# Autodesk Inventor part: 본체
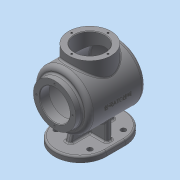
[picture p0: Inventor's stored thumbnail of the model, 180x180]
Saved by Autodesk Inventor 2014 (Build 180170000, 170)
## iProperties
Created: 2023-01
Part Number: 본체
Material: 일반
Document SubType Name: Modeling
Designer: dg
Density: 1 g/cm^3
Appearance: 기본값
Author: dg
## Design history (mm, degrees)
sketch "스케치1"
  geometry: L1 (0, 0)-(122, 0); L2 (0, 27)-(0, 38); L3 (0, 38)-(12, 38); L4 (12, 38)-(12, 50); L5 (12, 50)-(111.087, 50); L6 (0, 27)-(17, 27); L7 (17, 27)-(17, 45); L8 (17, 45)-(107.374, 45); A1 r 120 centre (2, 0) between (122, 0) and (111.087, 50); A2 r 110 centre (7, 0) between (117, 0) and (107.374, 45)
  constraints: 16 end point, 4 parallel, 4 point on circle, 3 perpendicular, 2 centre point, 2 horizontal alignment, 1 horizontal, 1 point on line, 1 vertical alignment
  dimensions: "d0" = 122 distance of L1.start L1.end; "d1" = 54 diameter of L6 L1; "d2" = 17 distance of L2.start L6.end; "d3" = 5 distance of L1.end A2.start; "d4" = 120 radius of A1; "d5" = 110 distance from line of L1.end L4; "d6" = 76 diameter of L3 L1; "d7" = 100 diameter of L5 L1; "d8" = 90 diameter of L8 L1; "d9" = 110 radius of A2
revolve "회전1" sketch "스케치1" stored, may be unused: angle "d10" = 90 deg
node "작업 평면1"
sketch "스케치2"
  geometry: L1 (0, 80)-(0, 46); L2 (-46, 80)-(-46, 46); L3 (46, 46)-(46, 80); A1 r 46 centre (0, 80) between (46, 80) and (-46, 80); A2 r 46 centre (0, 46) between (-46, 46) and (46, 46); 3 further points
  constraints: 8 end point, 5 point on circle, 4 tangent, 2 centre point, 1 coincident, 1 midpoint, 1 parallel, 1 vertical, 1 vertical alignment
  dimensions: "d12" = 126 dimension on A2 A1; "d13" = 92 distance between parallel lines of L3 L2
extrude "돌출1" join sketch "스케치2" distance "d14" = 10; taper "d15" = 0 deg
sketch "스케치3"
  geometry: L1 (-46, 80)-(-46, 46) reference; L2 (-35, 58)-(35, 58); L3 (35, 58)-(35, 68); L4 (35, 68)-(-35, 68); L5 (-35, 68)-(-35, 58); A1 r 46 centre (0, 80) between (46, 80) and (-46, 80) reference; 5 further points
  constraints: 8 end point, 3 midpoint, 2 parallel, 1 horizontal, 1 horizontal alignment, 1 perpendicular, 1 point on circle, 1 vertical alignment
  dimensions: "d16" = 10 distance of L2.end L3.end; "d17" = 70 distance of L3.end L4.end
extrude "돌출2" join sketch "스케치3" stored distance "d18" = 10; taper "d19" = 0 deg
sketch "스케치4"
  geometry: L1 (-46, 80)-(-46, 46) reference; L2 (-5, 103)-(5, 103); L3 (5, 103)-(5, 23); L4 (5, 23)-(-5, 23); L5 (-5, 23)-(-5, 103); A1 r 46 centre (0, 80) between (46, 80) and (-46, 80) reference; 5 further points
  constraints: 8 end point, 3 midpoint, 2 parallel, 1 horizontal, 1 horizontal alignment, 1 perpendicular, 1 point on circle, 1 vertical alignment
  dimensions: "d20" = 10 distance of L2.start L2.end; "d21" = 80 distance of L2.end L3.end
extrude "돌출3" join sketch "스케치4" stored distance "d22" = 10; taper "d23" = 0 deg
feature "면 기울기2" dims angle "d25" = 15 deg
feature "면 기울기3" dims angle "d26" = 15 deg
node "작업 평면2"
sketch "스케치5"
  geometry: C1 r 38 at (0, 63); 1 further point
  constraints: 1 centre point, 1 vertical alignment
  dimensions: "d28" = 76 diameter of C1; "d29" = 63 distance of point (0, 0) C1.centre
extrude "돌출4" join sketch "스케치5" stored distance "d30" = 10; taper "d31" = 0 deg
hole "구멍1" diameter "d34" = 54; stored, may be unused: countersink angle "d38" = 90 deg, drill point angle "d40" = 118 deg; dims "d32" = 10, "d33" = 10, "d35" = 6, "d36" = 4, "d37" = 2, "d39" = 8
sketch "스케치6"
  geometry: C1 r 27 at (0, 0) reference; 2 further points
  constraints: 1 vertical alignment
  dimensions: "d41" = 32.5 distance of C1.centre point (0, 32.5)
hole "구멍2" sketch "스케치6" at (0, 32.5) diameter "d42" = 3.242; stored, may be unused: countersink angle "d46" = 90 deg, drill point angle "d48" = 118 deg; dims "d43" = 8, "d44" = 4, "d45" = 2, "d47" = 10
sketch "스케치7"
  geometry: C1 r 38 at (0, 0) reference; 1 further point
  constraints: 1 vertical alignment
  dimensions: "d52" = 32.5 distance of C1.centre point (0, 32.5)
hole "구멍3" sketch "스케치7" at (0, 32.5) diameter "d53" = 3.242; stored, may be unused: countersink angle "d57" = 90 deg, drill point angle "d59" = 118 deg; dims "d54" = 8, "d55" = 4, "d56" = 2, "d58" = 10
chamfer "모따기1" distance "d63" = 1; stored, may be unused: second distance "d64" = 2, angle "d65" = 45 deg
fillet "모깎기1" dims "d66" = 8
sketch "스케치8"
  geometry: L1 (35, 68)-(35, 58) reference; L2 (-35, 58)-(-35, 68) reference; A1 r 46 centre (0, 80) between (46, 80) and (-46, 80) reference; 7 further points
  constraints: 3 horizontal alignment, 2 midpoint, 2 vertical alignment
  dimensions: "d67" = 60 distance of point (30, 93) point (-30, 93); "d68" = 30 horizontal distance of A1.centre point (-30, 93) (= 0.5 x d67); "d69" = 60 distance of point (30, 33) point (30, 93); "d70" = 30 vertical distance of point (35, 63) point (30, 33) (= 0.5 x d69)
hole "구멍4" sketch "스케치8" at (-30, 93), (30, 93), (30, 33), (-30, 33) diameter "d71" = 9; stored, may be unused: countersink angle "d75" = 90 deg, drill point angle "d77" = 118 deg; dims "d72" = 8, "d73" = 4, "d74" = 2, "d76" = 9
fillet "모깎기2" dims "d78" = 3
fillet "모깎기3" dims "d79" = 3
fillet "모깎기4" dims "d80" = 3
node "작업 평면3"
sketch "스케치9"
  geometry: L1 (64.456, -80)-(18.456, -80) reference; 2 further points
  constraints: 1 other
  dimensions: "d81" = 63 distance of point (1.456, 0) point (-61.544, 0); "d82" = 80 distance from line of L1 point (1.456, 0)
feature "엠보싱1" sketch "스케치9" dims "d0" = 122, "d1" = 54, "d2" = 17, "d3" = 5, "d4" = 120, "d5" = 110, "d6" = 76, "d7" = 100, "d8" = 90, "d9" = 110, "d12" = 126, "d13" = 92, "d83" = 0.5, "d84" = 0
node "솔리드1"
pattern_circular "원형 패턴1" dims angle "d50" = 360 deg
pattern_circular "원형 패턴2" dims angle "d61" = 360 deg
other parameters: "d27" = 64
